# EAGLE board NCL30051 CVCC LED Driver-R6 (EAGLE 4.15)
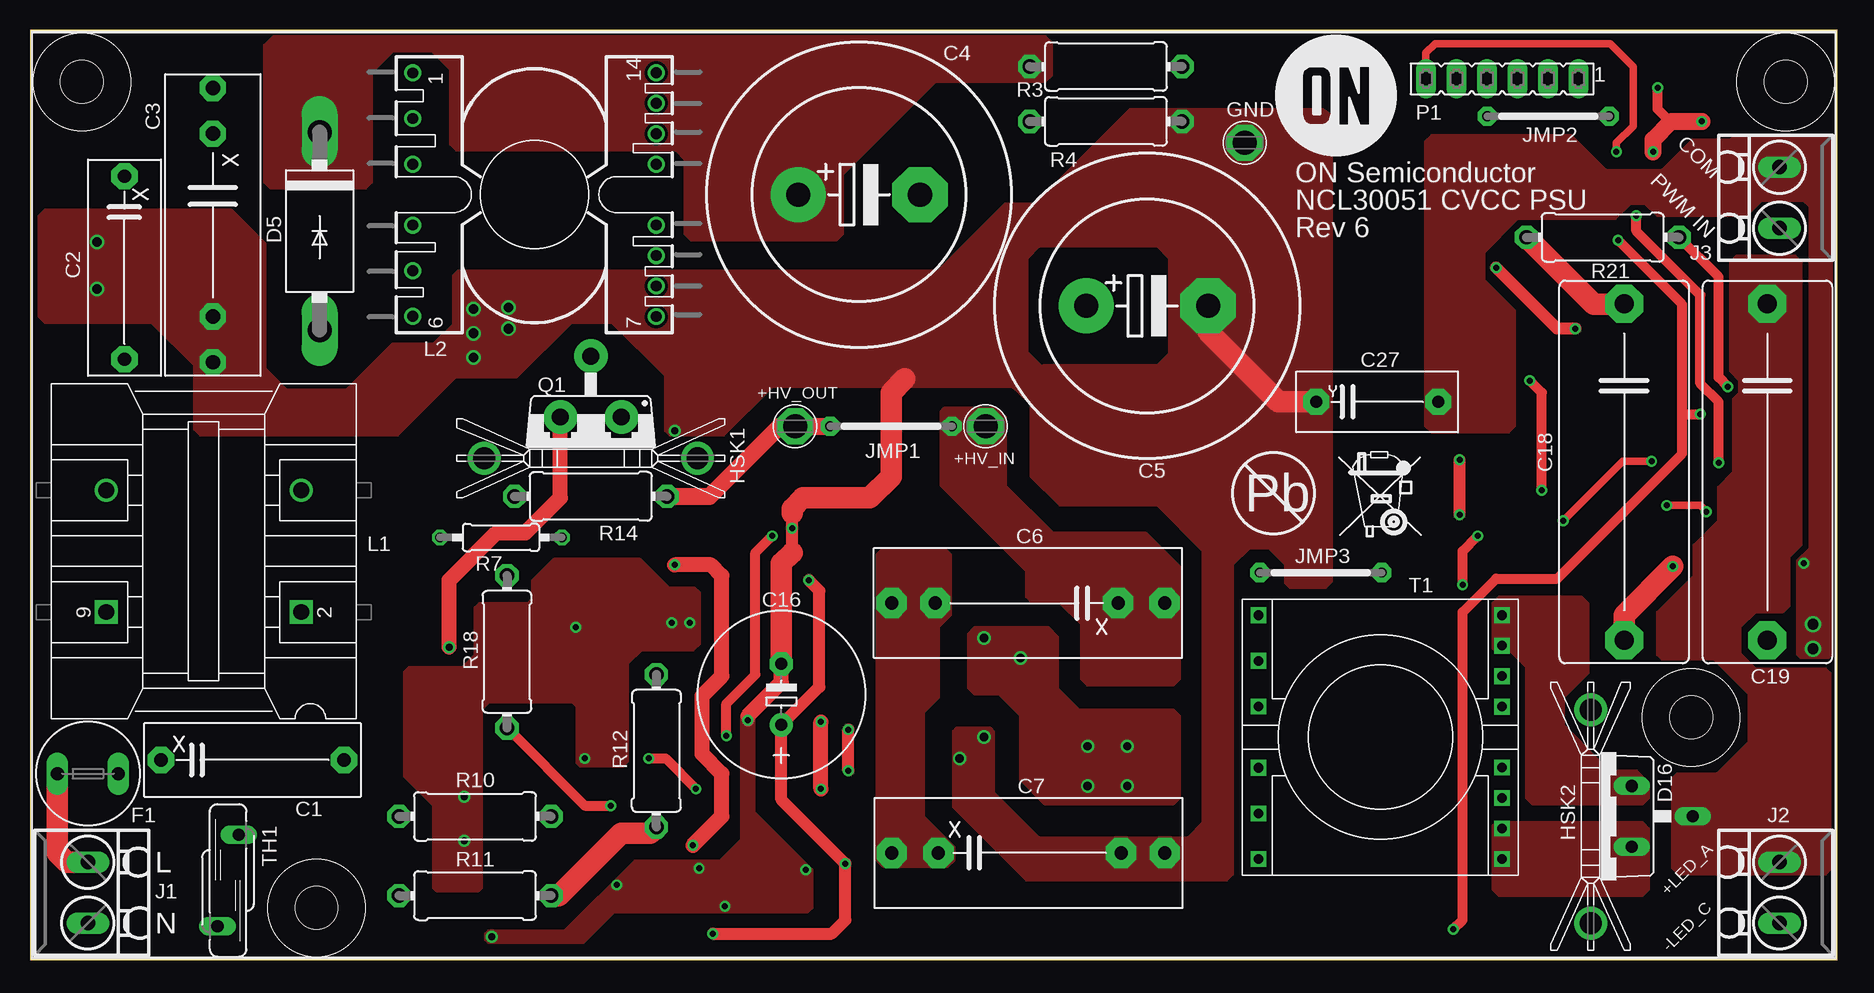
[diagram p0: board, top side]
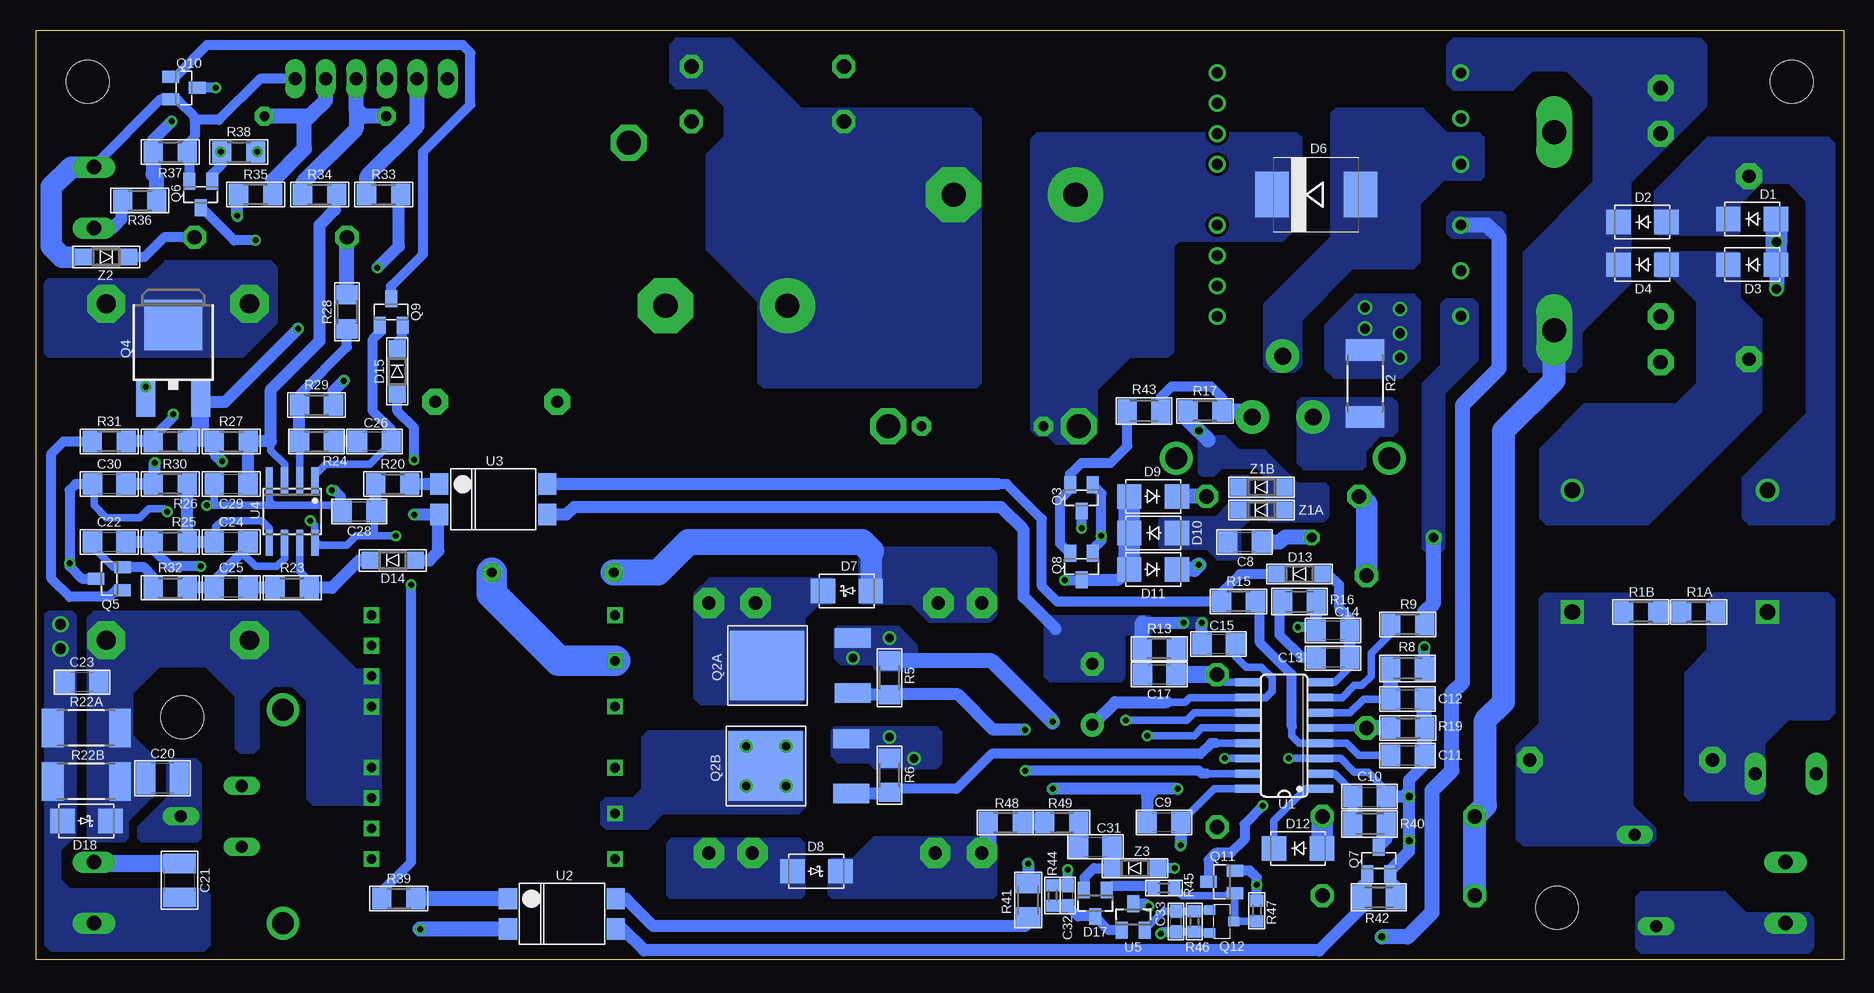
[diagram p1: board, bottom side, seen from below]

Size 150.62 x 77.47 mm. Coordinates in mm from the lower left corner, seen from the top.
Outline: 0,0 150.62,0 150.62,77.47 0,77.47 0,0
Copper layers (1*16): Top 0.035mm / dielectric 1.5mm / Bottom 0.035mm
Design rules "default": minimum track width 10mil, minimum drill 19mil, track to track 8mil, track to pad 8mil, pad to pad 8mil, via to via 8mil, smd to smd 8mil, copper to edge 10mil, drill to drill 8mil, minimum pad ring 10mil, minimum via ring 8mil, stop-mask expansion 4mil, vias tented up to drill 0mil, thermal gap 10mil
Holes 3.56 mm at 146.3,73.15 4.32,73.15 23.88,4.32 138.43,20.19

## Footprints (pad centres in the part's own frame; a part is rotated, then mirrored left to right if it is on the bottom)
PC_TEST_POINT = drill 2 octagon: 1 0,0
XC15B6 = drill 1.1 pad 2.184 octagon: 1 -7.62,0; 2 7.62,0
XC22.5B25X8MM = drill 1.2 pad 2.184 octagon: 1 -11.43,0; 2 11.43,0; 3 -7.62,0; 4 7.62,0
EB25D = drill 2.007 pad 4.597 round: + -5.08,0 | drill 2.007 pad 4.597 octagon: - 5.08,0
XC15_22.5B10 = drill 1.1 pad 2.54 octagon: 1 -7.62,0; 2 7.62,0; 3 -11.5,0; 4 11.25,0
C1206 = smd 1.6 x 1.8: 1 -1.4,0; 2 1.4,0
E5-13 = drill 1 pad 1.93 round: + -2.54,0 | drill 1 pad 1.93 octagon: - 2.54,0
C280-11X32 = drill 1.6 pad 3.175 octagon: 1 -14.016,0; 2 14.016,0
C1210 = smd 1.6 x 2.7: 1 -1.4,0; 2 1.4,0
YC10B5 = drill 1.016 pad 2.184 octagon: 1 -5.08,0; 2 5.08,0
C0603 = smd 1.1 x 1: 1 -0.85,0; 2 0.85,0
SMA-DIODE = smd 2.032 x 2.032: A 1.994,0; C -1.994,0
DO201-15 = drill 2 long: A 8.255,0; C -8.255,0
SMC = smd 2.8 x 3.8: A 3.7,0; C -3.7,0
SMA = smd 2.032 x 2.032: A 1.994,0; C -1.994,0
SOD123 = smd 1.4 x 1.4: A 1.9,0; C -1.9,0
TO220CSH = drill 1.016 long: A1 -2.54,-2.54; A2 2.54,-2.54; C 0,-7.62
SOT23 = smd 1 x 1.4: 1 -0.95,-1.1; 2 0.95,-1.1; 3 0,1.1
TR5 = drill 1.1 pad 1.778 long: 1 -2.54,0; 2 2.54,0
AAVID-542502D00000 = drill 1.829 round: 1 -8.89,0; 2 8.89,0
2-PIN = drill 1.2 long: + -2.54,0; - 2.54,0
10 = drill 0.813 pad 1.6 octagon: 1 -5.08,0; 2 5.08,0
E3491-AL = drill 1.3 square: 2 -5.08,-8.128; 9 -5.08,8.128 | drill 1.3 round: 4 5.08,-8.128; 7 5.08,8.128
PQ20/20 = drill 0.9 round: 1 -10.14,-10.15; 2 -6.34,-10.15; 3 -2.54,-10.15; 4 2.54,-10.15; 5 6.34,-10.15; 6 10.14,-10.15; 7 10.16,10.15; 8 7.62,10.15; 9 5.08,10.15; 10 2.54,10.15; 11 -2.54,10.15; 12 -5.08,10.15; 13 -7.62,10.15; 14 -10.16,10.15
FE06 = drill 1.1 pad 1.422 long: 1 -6.35,0; 2 -3.81,0; 3 -1.27,0; 4 1.27,0; 5 3.81,0; 6 6.35,0
IW220-BENT = drill 1.4 pad 2.794 round: D 0,-7.62; G -2.54,-2.54; S 2.54,-2.54
DPAK = smd 1.6 x 2.997: 1 -2.286,-4.064; 3 2.286,-4.064 | smd 5.791 x 6.198: 4 0,3.099
SOT23-BEC = smd 1 x 1.4: B -0.95,-1.1; C 0,1.1; E 0.95,-1.1
DPAK' = smd 1.6 x 3: 1 -2.28,-4.04; 3 2.28,-4.04 | smd 4.826 x 4.191: 4 0,2.096
SOT-23 = smd 1 x 1.4: D 0,1.1; G -0.95,-1.1; S 0.95,-1.1
MICRO3 = smd 0.8 x 0.9: 1 -0.95,-1; 2 0.95,-1; 3 0,1
R1206 = smd 1.6 x 1.803: 1 -1.422,0; 2 1.422,0
R2512 = smd 1.8 x 3.2: 1 -2.8,0; 2 2.8,0
0411/12 = drill 1.2 pad 1.93 octagon: 1 -6.35,0; 2 6.35,0
0207/10 = drill 0.813 octagon: 1 -5.08,0; 2 5.08,0
M1206 = smd 1.6 x 2: 1 -1.4,0; 2 1.4,0
R0603 = smd 1 x 1.1: 1 -0.85,0; 2 0.85,0
PQ20/20' = drill 0.8 square: 1 -10.16,-10.15; 2 -6.36,-10.15; 3 -2.55,-10.15; 4 2.55,-10.15; 5 6.36,-10.15; 6 10.16,-10.15; 7 10.16,10.15; 8 7.62,10.15; 9 5.08,10.15; 10 2.54,10.15; 11 -2.54,10.15; 12 -5.08,10.15; 13 -7.62,10.15; 14 -10.16,10.15
S10K17 = drill 1.016 long: 1 -0.889,-3.81; 2 0.889,3.81
SOIC16 = smd 0.66 x 2.032: 1 -4.445,-3.073; 2 -3.175,-3.073; 3 -1.905,-3.073; 4 -0.635,-3.073; 5 0.635,-3.073; 6 1.905,-3.073; 7 3.175,-3.073; 8 4.445,-3.073; 9 4.445,3.073; 10 3.175,3.073; 11 1.905,3.073; 12 0.635,3.073; 13 -0.635,3.073; 14 -1.905,3.073; 15 -3.175,3.073; 16 -4.445,3.073
4PIN-SURFMOUNT-OPTO = smd 1.524 x 1.778: 1 4.496,-1.27; 2 4.496,1.27; 3 -4.496,1.27; 4 -4.496,-1.27
SO08 = smd 0.6 x 2.2: 1 -1.905,-2.6; 2 -0.635,-2.6; 3 0.635,-2.6; 4 1.905,-2.6; 5 1.905,2.6; 6 0.635,2.6; 7 -0.635,2.6; 8 -1.905,2.6
SOT-23' = smd 1 x 1.4: 1 -0.95,-1.1; 2 0.95,-1.1; 3 0,1.1

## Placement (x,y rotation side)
+HV_IN  TP5010-5014  [PC_TEST_POINT]  79.63,44.45 0 top
+HV_OUT  TP5010-5014  [PC_TEST_POINT]  63.75,44.45 0 top
C1  0.1uF  [XC15B6]  18.54,16.64 0 top
C2  0.1uF  [XC15B6]  7.87,57.66 270 top
C3  0.1uF  [XC22.5B25X8MM]  15.24,61.21 270 top
C4  150uF/400V  [EB25D]  69.09,63.75 0 top
C5  150uF/400V  [EB25D]  93.09,54.48 0 top
C6  0.1uF/400V  [XC15_22.5B10]  83.06,29.72 180 top
C7  0.1uF/400V  [XC15_22.5B10]  83.31,8.89 0 top
C8  5.6nF  [C1206]  49.91,34.8 180 bottom
C9  0.22uF  [C1206]  56.64,11.43 180 bottom
C10  820pF  [C1206]  39.5,13.59 0 bottom
C11  0.1uF  [C1206]  36.32,17.02 0 bottom
C12  100pF  [C1206]  36.32,21.72 0 bottom
C13  0.68uF  [C1206]  42.55,25.15 180 bottom
C14  1nF  [C1206]  42.55,27.43 180 bottom
C15  0.1uF  [C1206]  52.07,26.29 180 bottom
C16  330uF/35V  [E5-13]  62.61,22.1 90 top
C17  1.2nF  [C1206]  57.02,23.75 180 bottom
C18  4.7uF/100V  [C280-11X32]  132.84,40.64 270 top
C19  4.7uF/100V  [C280-11X32]  144.78,40.64 270 top
C20  0.1uF/100V  [C1210]  140.08,15.11 180 bottom
C21  0.1uF/100V  [C1210]  138.68,6.6 270 bottom
C22  1.0uF  [C1206]  144.53,34.8 180 bottom
C23  0.1uF  [C1206]  146.81,23.11 180 bottom
C24  1nF  [C1206]  134.37,34.8 180 bottom
C25  1.0uF  [C1206]  134.37,30.99 180 bottom
C26  0.1uF  [C1206]  122.43,43.18 180 bottom
C27  2.2nF/1KV  [YC10B5]  112.27,46.48 0 top
C28  1.0uF  [C1206]  123.7,37.34 180 bottom
C29  10nF  [C1206]  134.37,39.62 180 bottom
C30  0.1uF  [C1206]  144.53,39.62 180 bottom
C31  220pF  [C1206]  62.36,9.4 0 bottom
C32  100nF  [C0603]  64.64,5.33 90 bottom
C33  220pF  [C0603]  55.63,3.18 90 bottom
D1  MRA4007  [SMA-DIODE]  7.62,61.72 0 bottom
D2  MRA4007  [SMA-DIODE]  16.76,61.47 0 bottom
D3  MRA4007  [SMA-DIODE]  7.62,57.91 0 bottom
D4  MRA4007  [SMA-DIODE]  16.76,57.91 0 bottom
D5  1N5406  [DO201-15]  24.13,60.71 270 top
D6  MURS360BT  [SMC]  43.94,63.75 0 bottom
D7  MURA160  [SMA]  83.06,30.73 0 bottom
D8  MURA160  [SMA]  85.6,7.37 180 bottom
D9  MRA4007  [SMA-DIODE]  57.53,38.61 180 bottom
D10  MURA160  [SMA-DIODE]  57.53,35.56 0 bottom
D11  MURA160  [SMA-DIODE]  57.53,32.51 180 bottom
D12  MRA4007  [SMA-DIODE]  45.47,9.27 0 bottom
D13  MMSD4148T  [SOD123]  45.34,32.13 0 bottom
D14  MMSD4148T  [SOD123]  120.9,33.27 0 bottom
D15  MMSD4148T  [SOD123]  120.52,49.02 270 bottom
D16  MBRF10H150  [TO220CSH]  130.94,11.94 90 top
D17  BAV70  [SOT23]  62.36,4.7 180 bottom
D18  MBRA340  [SMA]  146.43,11.56 180 bottom
E$2  [ON2]  108.84,72.01 0 top
F1  1.5A  [TR5]  4.83,15.49 0 top
GND  TP5010-5014  [PC_TEST_POINT]  101.22,68.07 0 top
HSK1  AAVID-542502D00000  [AAVID-542502D00000]  46.74,41.78 180 top
HSK2  AAVID-542502D00000  [AAVID-542502D00000]  130.05,11.94 90 top
J1  [2-PIN]  4.83,5.59 270 top
J2  [2-PIN]  145.8,5.59 90 top
J3  [2-PIN]  145.8,63.5 90 top
JMP1  J10MM  [10]  71.76,44.45 0 top
JMP2  J10MM  [10]  126.52,70.28 0 top
JMP3  J10MM  [10]  107.57,32.26 0 top
L1  2.9mH  [E3491-AL]  14.48,34.04 90 top
L2  700uH  [PQ20/20]  42.04,63.75 270 top
P1  [FE06]  122.68,73.41 180 top
Q1  SPP11N60C3  [IW220-BENT]  46.74,42.67 180 top
Q2A  NDD04N60ZT  [DPAK]  86.61,24.51 90 bottom
Q2B  NDD04N60ZT  [DPAK]  86.74,16.13 90 bottom
Q3  MMBT2907A  [SOT23-BEC]  63.5,38.48 180 bottom
Q4  MJD243G  [DPAK']  139.19,50.8 0 bottom
Q5  2N7002KT1G  [SOT23]  144.53,31.75 90 bottom
Q6  MMBTA06LT1G  [SOT23-BEC]  136.91,63.75 180 bottom
Q7  MMBTA06LT1G  [SOT23-BEC]  38.74,8.26 0 bottom
Q8  MMBTA06LT1G  [SOT23-BEC]  63.5,32.77 180 bottom
Q9  MMBT2907A  [SOT23-BEC]  121.03,53.98 0 bottom
Q10  MMUN2212L  [SOT23-BEC]  138.3,72.64 270 bottom
Q11  2N7002  [SOT-23]  51.82,6.48 90 bottom
Q12  BSS84  [MICRO3]  51.82,3.18 270 bottom
R1A  560K  [R1206]  12.07,28.96 0 bottom
R1B  560K  [R1206]  16.89,28.96 0 bottom
R2  0.15/0.5W  [R2512]  39.88,48.01 270 bottom
R3  560K/0.5W  [0411/12]  89.66,74.42 180 top
R4  560K/0.5W  [0411/12]  89.66,69.85 180 top
R5  10K  [R1206]  79.5,23.5 270 bottom
R6  10K  [R1206]  79.5,15.37 270 bottom
R7  10/0.25W  [0207/10]  39.24,35.18 180 top
R8  1.2K  [M1206]  36.32,24.26 0 bottom
R9  26.7K  [R1206]  36.32,27.94 0 bottom
R10  4.7K/0.5W  [0411/12]  37.08,11.94 0 top
R11  680K/0.5W  [0411/12]  37.08,5.33 180 top
R12  680K/0.5W  [0411/12]  52.2,17.4 270 top
R13  OPEN  [R1206]  57.02,25.91 0 bottom
R14  2.7M/0.5W  [0411/12]  46.74,38.61 0 top
R15  2.7K  [R1206]  50.42,29.85 0 bottom
R16  1K  [M1206]  45.34,29.85 180 bottom
R17  10K  [R1206]  53.21,45.72 0 bottom
R18  2.7M/0.5W  [0411/12]  39.75,25.65 90 top
R19  26.7K  [R1206]  36.32,19.3 180 bottom
R20  2.2K  [R1206]  120.9,39.62 180 bottom
R21  4.7K/0.5W  [0411/12]  131.06,60.2 0 top
R22A  0.1/0.5W  [R2512]  146.43,19.3 180 bottom
R22B  0.1/0.5W  [R2512]  146.43,14.86 180 bottom
R23  100K  [R1206]  129.29,30.99 180 bottom
R24  100K  [R1206]  127.25,43.18 180 bottom
R25  2.7K  [R1206]  139.45,34.8 180 bottom
R26  68K  [R1206]  139.45,39.62 0 bottom
R27  6.2K  [R1206]  134.37,43.18 180 bottom
R28  78.7K  [R1206]  124.71,53.98 90 bottom
R29  3.9K  [R1206]  127.25,46.23 180 bottom
R30  5.1K  [R1206]  139.45,43.18 180 bottom
R31  100  [R1206]  144.53,43.18 0 bottom
R32  2.7K  [R1206]  139.45,30.99 180 bottom
R33  10  [R1206]  121.67,63.75 180 bottom
R34  10  [R1206]  127,63.75 180 bottom
R35  10  [R1206]  132.33,63.75 0 bottom
R36  10K  [R1206]  141.99,63.25 180 bottom
R37  10K  [R1206]  139.45,67.31 180 bottom
R38  10K  [R1206]  133.73,67.31 180 bottom
R39  2.7K  [R1206]  120.4,5.08 180 bottom
R40  1.2K  [M1206]  39.5,11.3 0 bottom
R41  10K  [M1206]  67.95,4.95 270 bottom
R42  5.1K  [M1206]  38.74,5.21 180 bottom
R43  10  [M1206]  58.29,45.72 0 bottom
R44  10K  [R0603]  65.91,5.33 270 bottom
R45  33K  [R0603]  56.64,5.97 0 bottom
R46  4.7K  [R0603]  54.1,3.18 270 bottom
R47  33K  [R0603]  48.9,4.06 270 bottom
R48  24K  [R1206]  69.85,11.43 180 bottom
R49  24K  [R1206]  65.15,11.43 180 bottom
T1  [PQ20/20']  112.52,18.54 270 top
TH1  [S10K17]  16.51,6.6 0 top
U1  NCL30051  [SOIC16]  46.61,18.67 90 bottom
U2  SFH6156A-4  [4PIN-SURFMOUNT-OPTO]  106.81,3.81 180 bottom
U3  SFH6156A-4  [4PIN-SURFMOUNT-OPTO]  112.52,38.35 180 bottom
U4  NCS1002  [SO08]  129.29,37.34 180 bottom
U5  TLV431A  [SOT-23']  59.18,3.56 0 bottom
U$3  [WEEE_SMALL]  112.65,36.58 0 top
Z1A  MMSZ5248B  [SOD123]  48.51,37.47 0 bottom
Z1B  MMSZ5248B  [SOD123]  48.51,39.37 0 bottom
Z2  MMSZ5245B  [SOD123]  144.78,58.55 180 bottom
Z3  MMSZ5248B  [SOD123]  59.06,7.62 0 bottom

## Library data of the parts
+HV_IN +HV_OUT GND = testpad
C1-C33 R1A R1B R2-R21 R22A R22B R23-R49 = rcl
D1-D18 Z1A Z1B Z2 Z3 = diode
E$2 = loga
F1 = fuse
HSK1 HSK2 = heatsink
J1-J3 = My CONNECTOR lib
JMP1-JMP3 = jumper
L1 = MY  INDUCTOR Lib
L2 = My X-former-2
P1 = con-lsta
Q1 Q2A Q2B Q12 = transistor-power
Q3 Q9 = transistor-pnp
Q4 = transistor
Q5 = transistor-small-signal
Q6-Q8 Q10 = transistor-npn2
Q11 = transistor-fet
T1 = My X-former
TH1 = varistor
U1 U5 = My IC Lib
U2 U3 = optocoupler
U4 = linear
U$3 = My Sign Lib

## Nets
N$1: C1.1 F1.2 L1.9 R1A.2
N$2: J1.- TH1.1
N$3: C2.1 D1.C D2.A L1.7
N$4: C1.2 L1.2 R1B.1 TH1.2
N$5: C10.1 R40.1 U1.2
N$6: C2.2 D3.C D4.A L1.4
N$7: D6.A L2.3 Q1.D
N$8: Q1.S R2.2 R8.2
N$9: +HV_OUT.1 C4.+ D5.C D6.C D9.C JMP1.1 R3.2 R14.2
N$10: C3.1 C3.3 D2.C D4.C D5.A L2.1 R10.1 R11.2
N$11: C4.- C5.+ R3.1 R4.2
N$12: Q2A.1 R5.2 U1.15
N$13: Q2B.1 R6.2 U1.13
N$14: Q3.E Q8.E R43.1
N$15: L2.6 R7.2 R9.2
N$16: C9.2 Q2A.3 Q2B.4 R5.1 T1.5 U1.14
N$17: +HV_IN.1 C6.1 C6.3 D7.C JMP1.2 Q2A.4
N$18: Q3.B Q8.B U1.12
N$19: C12.1 R8.1 U1.6
N$20: C6.2 C6.4 C7.1 C7.3 D7.A D8.C JMP3.1 R48.2
N$21: C8.1 R7.1
N$22: R9.1 U1.7
N$23: D12.C U1.1
N$24: C11.1 R15.2 U1.4
N$25: R11.1 R12.2
N$26: C17.1 R12.1 R13.2 U1.9
N$27: D16.A1 T1.7 T1.8
N$28: C13.1 C14.1 D13.A U1.8
N$29: C13.2 R16.2
N$30: Q1.G R17.2 R43.2
N$31: R14.1 R18.2
N$32: C21.2 C23.2 C27.2 C28.2 C29.2 C30.2 D18.A J2.+ J3.- P1.1 Q5.3 Q6.E Q10.E R22A.2 R22B.2 R29.1 R37.1 U4.4 Z2.A
N$33: C8.2 D10.A Z1A.C Z1B.C
N$34: Q7.C R40.2
N$35: C15.1 C16.+ C33.1 D9.A D10.C D11.A Q8.C Q12.2 R41.1 R46.2 U1.10
N$36: C9.1 D11.C U1.16
N$37: R39.1 U2.1
N$38: Q11.D R18.1 R19.2 U1.5
N$39: Q6.C R30.2 R31.2 U2.2
N$40: R20.1 U3.1
N$41: D14.A D15.A U3.2
N$42: C18.2 C19.2 C20.2 C22.1 C23.1 D18.C R22A.1 R22B.1 R25.2 T1.9 T1.10 T1.11 T1.12
N$43: D16.A2 T1.13 T1.14
N$44: C3.2 C3.4 C5.- C7.2 C7.4 C10.2 C11.2 C12.2 C14.2 C15.2 C16.- C17.2 C27.1 C32.2 D1.A D3.A D8.A GND.1 L2.4 Q2B.3 Q3.C Q7.E Q11.S R2.1 R4.1 R6.1 R13.1 R16.1 R17.1 R19.1 R42.1 R44.1 R47.1 U1.3 U1.11 U3.3 U5.3 Z1A.A Z1B.A Z3.A
N$45: D13.C R15.1 U3.4
N$46: F1.1 J1.+
N$47: D14.C R23.1 U4.7
N$48: D12.A R10.2
N$49: Q7.B R42.2 U2.3
N$50: C29.1 R27.1 R34.1 U4.3
N$51: C30.1 R26.1 R35.1
N$52: C25.1 R23.2
N$53: C24.1 C25.2 R32.1 U4.6
N$54: Q4.1 R21.2 Z2.C
N$55: C26.1 Q9.B U4.1
N$56: C28.1 Q4.3 R20.2 R27.2 R30.1 R33.1 R39.2 U4.8
N$57: C26.2 R24.1
N$58: R24.2 R28.1 R29.2 U4.2
N$59: C24.2 R25.1 R26.2 U4.5
N$60: R41.2 U2.4
N$61: C22.2 Q5.2 R32.2
N$62: Q5.1 R31.1
N$63: Q6.B Q10.C R36.1 R37.2 R38.2
N$64: JMP3.2 T1.2
N$65: J3.+ R36.2
N$66: JMP2.2 P1.2 R35.2
N$67: JMP2.1 P1.3 R34.2
N$68: C18.1 C19.1 C20.1 C21.1 D16.C J2.- Q4.4 R21.1 R28.2
N$69: P1.5 R33.2
N$70: P1.6 R38.1
N$71: R1A.1 R1B.2
N$72: D15.C Q9.E
N$73: R48.1 R49.2
N$74: C31.1 R49.1
N$75: Q9.C Q10.B
N$76: C31.2 D17.2 Z3.C
N$77: C32.1 D17.3 R44.2 U5.1
N$79: D17.1 R45.1
N$80: Q11.G Q12.3 R45.2 R47.2
N$81: C33.2 Q12.1 R46.1 U5.2

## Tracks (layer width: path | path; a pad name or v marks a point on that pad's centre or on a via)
N$1
  pour Bottom (no thermals): 6.6,13.72 6.6,18.03 4.57,20.07 1.27,20.07 0.76,20.57 0.76,29.97 1.27,30.48 10.8,30.48 11.3,29.97 11.3,25.78 13.21,23.88 13.21,13.72 12.83,13.34 6.99,13.34
N$2
  pour Bottom (no thermals): 16.89,0.64 2.92,0.64 2.54,1.02 2.54,3.43 2.92,3.81 8.13,3.81 9.91,5.59 16.89,5.59 17.27,5.21 17.27,1.02
N$3
  pour Bottom (no thermals): 6.86,64.77 4.57,64.77 3.05,63.25 3.05,45.47 8.38,40.13 8.38,36.83 7.87,36.32 1.27,36.32 0.76,36.83 0.76,67.95 1.27,68.45 11.3,68.45 15.75,64.01 15.75,60.71 15.49,60.45 8.89,60.45 8.64,60.71 8.64,62.99
N$4
  pour Bottom (no thermals): 26.67,9.53 27.18,10.03 27.18,17.78 25.27,19.69 25.27,30.1 24.89,30.48 18.03,30.48 17.65,30.1 17.65,12.83 15.75,10.92 15.75,10.03 16.26,9.53
N$5
  Bottom 0.61: C10.1 40.89,13.97 42.42,15.49 U1.2
  Bottom 0.813: R40.1 C10.1
N$6
  pour Bottom (isolate 1.27, no thermals): 16.26,36.32 6.86,45.72 6.86,53.34 8.64,55.12 8.64,58.67 8.89,58.93 15.49,58.93 15.75,58.67 15.75,57.15 15.49,56.9 14.22,56.9 12.19,54.86 12.19,48.01 13.97,46.23 21.59,46.23 25.27,42.55 25.27,36.83 24.77,36.32
N$7
  pour Bottom (no thermals): 45.21,49.53 45.21,53.34 40.89,57.66 35.81,57.66 35.31,58.17 35.31,62.99 33.27,65.02 30.23,65.02 29.97,65.28 29.97,68.45 30.35,68.83 33.02,68.83 35.05,70.87 42.29,70.87 42.67,70.49 42.67,60.2 48.26,54.61 48.26,49.53 47.75,49.02 45.72,49.02
N$8  (via drill 0.6)
  Top 1.27: Q1.S 44.2,38.48 41.28,35.56 38.86,35.56 34.93,31.62 v34.93,26.04
  Bottom 1.016: R8.2 v34.93,26.04
  Bottom 1.27: R8.2
  pour Bottom (no thermals): 38.61,43.69 37.59,43.69 37.21,44.07 37.21,46.36 37.59,46.74 45.21,46.74 45.47,46.48 45.47,41.4 44.96,40.89 40.13,40.89 39.88,41.15 39.88,42.42
N$9
  Top 1.422: R14.2 56.64,38.61 62.48,44.45 +HV_OUT.1 JMP1.1
  Bottom 1.27: R14.2 D9.C
  pour Top (isolate 0.254, no thermals): 19.56,64.77 19.56,76.2 20.32,76.96 84.58,76.96 85.09,76.45 85.09,73.66 84.58,73.15 75.44,73.15 67.69,65.41 67.69,60.45 67.18,59.94 55.12,59.94 54.61,60.45 54.61,66.68 53.85,67.44 35.56,67.44 35.05,67.95 35.05,74.17 33.53,75.69 30.23,75.69 28.45,73.91 28.45,64.77 27.94,64.26 20.07,64.26
  pour Bottom (isolate 0.254, no thermals): 45.21,61.47 45.21,68.45 45.59,68.83 67.18,68.83 67.69,68.33 67.69,44.2 67.18,43.69 66.29,43.69 65.66,43.05 63.25,43.05 62.23,44.07 62.23,47.5 59.44,50.29 56.26,50.29 55.88,50.67 55.88,59.44 55.37,59.94 46.74,59.94
N$10
  Bottom 1.93: R11.2 R10.1 29.85,12.83 29.85,19.94 28.32,21.46 28.32,44.07 24.13,48.26 D5.A
  pour Bottom (no thermals): 17.78,56.39 17.78,64.77 11.43,71.12 11.43,76.2 11.94,76.71 32.51,76.71 33.02,76.2 33.02,73.03 32.51,72.52 27.56,72.52 25.91,74.17 23.11,74.17 20.83,71.88 20.83,64.77 26.67,58.93 26.67,49.53 26.16,49.02 22.35,49.02 21.84,49.53 21.84,52.32
N$11
  pour Bottom (no thermals): 71.88,48.13 71.88,70.1 72.64,70.87 86.87,70.87 92.71,76.71 97.28,76.71 97.79,76.2 97.79,73.15 97.28,72.64 94.74,72.64 93.22,71.12 93.22,68.58 94.74,67.06 94.74,59.18 90.42,54.86 90.42,48.13 90.04,47.75 81.41,47.75 72.26,47.75
N$12  (via drill 0.5)
  Top 1.016: v68.2,15.75 v68.2,19.18
  Bottom 0.61: U1.15 53.09,15.49
  Bottom 0.813: 79.5,22.1 R5.2 | 53.09,15.49 53.47,15.49 53.72,15.75 v68.2,15.75
  Bottom 1.016: 79.5,22.1 73.79,22.1 70.87,19.18 v68.2,19.18 | Q2A.1 82.55,22.1 82.53,22.07 R5.2
N$13
  Bottom 0.61: U1.13 52.32,18.03
  Bottom 0.813: Q2B.1 82.8,13.97 | R6.2 79.53,13.95 | R6.2 79.4,13.95 79.12,14.22 73.91,14.22 70.99,17.15 53.59,17.15 52.71,18.03 52.32,18.03 | R6.2 79.5,13.84
  Bottom 1.016: 79.5,13.84 Q2B.1 82.8,13.84
N$14
  Bottom 0.813: Q8.E 64.45,33.84 65.28,34.67 65.28,38.35 64.39,39.24 64.45,39.3 64.45,39.56 64.47,39.58 | 64.47,39.58 64.52,39.62 | 64.47,39.58 Q3.E 64.45,40.45 63.5,41.4 61.09,41.4 59.69,42.8 R43.1
N$15
  Bottom 1.27: R9.2 34.93,27.94 34.93,28.96 34.16,29.72 R7.2
  pour Bottom (no thermals): 33.27,34.29 33.27,47.24 30.48,50.04 30.48,54.61 30.86,54.99 33.15,54.99 33.53,54.61 33.53,49.53 35.05,48.01 35.05,34.29 34.8,34.04 33.53,34.04
N$16  (via drill 0.5, 0.7)
  Top 0.813: v51.56,16.76 52.96,16.76 v55.5,14.22
  Top 1.27: v65.91,14.22 v65.91,19.81
  Bottom 0.61: U1.14 v51.56,16.76
  Bottom 0.813: 58.04,11.81 C9.2
  Bottom 1.016: 57.4,14.22 v65.91,14.22 | v55.5,14.22 57.4,14.22 | 58.04,11.81 58.04,13.59 57.4,14.22
  Bottom 1.27: v65.91,19.81 70.99,24.89 79.5,24.89 R5.1
  other vias: 79.5,26.8 88.14,17.78 91.44,17.78 88.14,14.48 91.44,14.48 82.55,25.15
  pour Top (no thermals): 95.25,12.95 84.58,12.95 82.55,14.99 82.55,20.32 80.77,22.1 78.74,22.1 78.23,22.61 78.23,27.18 78.74,27.69 84.84,27.69 85.6,26.92 85.6,22.61 87.38,20.83 95.25,20.83 95.76,20.32 95.76,13.46
  pour Bottom (no thermals): 87.12,12.19 98.43,12.19 99.7,10.92 103.12,10.92 103.51,11.3 103.51,13.08 103.12,13.46 100.84,13.46 100.08,14.22 100.08,18.54 99.57,19.05 86.87,19.05 86.61,18.8 86.61,12.7
  pour Bottom (no thermals): 77.22,26.16 78.74,27.69 83.82,27.69 84.07,27.43 84.07,25.15 83.57,24.64 81.03,24.64 80.52,24.13 77.6,24.13 77.22,24.51
N$17
  pour Bottom (no thermals): 86.61,21.84 86.61,28.45 85.34,29.72 84.33,29.72 84.07,29.97 84.07,31.5 84.33,31.75 94.49,31.75 95.76,30.48 95.76,21.84 95.25,21.34 87.12,21.34
  pour Top (no thermals): 95.25,22.86 88.14,22.86 87.63,23.37 87.63,27.94 85.85,29.72 83.57,29.72 83.06,30.23 83.06,32.39 75.95,39.5 75.95,45.72 76.2,45.97 80.52,45.97 81.28,45.21 81.28,39.5 85.22,35.56 92.96,35.56 95.76,32.77 95.76,23.37
N$18  (via drill 0.5)
  Top 0.813: v61.85,35.31 60.45,33.91 60.45,23.75 58.04,21.34 v58.04,18.67
  Bottom 0.61: U1.12 53.47,19.3 54.1,18.67 v58.04,18.67
  Bottom 0.813: Q3.B 62.55,39.56 61.85,38.86 v61.85,35.31 61.85,34.93 62.55,34.22 Q8.B
N$19
  Bottom 0.61: U1.6 41.15,20.57 40.01,21.72 C12.1
  Bottom 1.016: R8.1 37.59,24.26 37.72,24.13
  Bottom 1.27: C12.1 37.72,24.13
N$20
  Bottom 1.422: C7.3 71.76,8.89 71.27,9.37 R48.2
  Bottom 1.778: D7.A 81.03,30.73 81.03,34.04
  Bottom 2.184: JMP3.1 98.81,32.26 96.27,34.8 81.79,34.8 81.03,34.04
  pour Bottom (no thermals): 70.61,28.7 70.61,33.78 71.12,34.29 81.53,34.29 82.04,33.78 82.04,29.97 81.79,29.72 77.72,29.72 76.2,28.19 71.12,28.19
  pour Bottom (no thermals): 70.61,5.46 70.61,9.65 71.12,10.16 80.77,10.16 82.55,8.38 84.33,8.38 84.58,8.13 84.58,5.46 84.33,5.21 70.87,5.21
  pour Top (no thermals): 70.61,8.26 70.61,33.78 71.12,34.29 76.2,34.29 76.71,33.78 76.71,28.7 75.69,27.69 75.69,21.84 74.42,20.57 74.42,11.94 76.96,9.4 76.96,8.26 76.45,7.75 71.12,7.75
N$21
  Bottom 1.27: R7.1 46.61,35.18 46.99,34.8 C8.1
N$22
  Bottom 0.61: U1.7 41.78,21.84 40.77,22.86 40.13,22.86 39.37,23.62 39.37,25.53 37.72,27.18 37.72,27.94 R9.1
N$23
  Bottom 0.61: U1.1 44.83,14.22 47.5,11.56 47.5,9.27 D12.C
N$24
  Bottom 0.61: C11.1 40.39,17.02 41.4,18.03 U1.4 45.34,18.03 45.97,18.67 45.97,19.43
  Bottom 0.813: 45.97,19.43 45.97,23.75 48.64,26.42 48.64,29.46 49.02,29.85 R15.2
N$25
  Top 1.778: R12.2 51.69,10.54 49.28,10.54 44.07,5.33 R11.1
N$26
  Bottom 0.61: U1.9 51.56,23.11 R12.1
  Bottom 1.422: R12.1 C17.1 55.6,23.77 R13.2
N$27
  pour Top (no thermals): 121.92,5.84 121.92,11.18 122.17,11.43 134.37,11.43 134.87,10.92 134.87,5.84 134.37,5.33 122.43,5.33
N$28
  Bottom 0.61: U1.8 42.42,23.11 41.15,24.38 C13.1
  Bottom 0.813: C14.1 41.15,28.45 42.04,29.34 42.04,31.24 42.93,32.13 D13.A
  Bottom 1.016: C14.1 C13.1
N$29
  Bottom 0.813: C13.2 45.09,25.15 46.99,27.05 46.99,29.59 R16.2
N$30
  Bottom 0.813: R43.2 56.89,46.87 56.01,47.75 52.71,47.75 51.82,46.86 51.82,45.72
  Bottom 1.27: Q1.G 49.78,45.72 51.82,45.72 R17.2
N$31
  Bottom 1.778: R18.2 39.75,37.97 R14.1
N$32  (via drill 0.5, 0.9)
  Top 0.61: v136.4,37.85 139.19,37.85 v139.7,37.34
  Top 0.813: v124.97,48.26 125.98,47.24 v125.98,39.12
  Bottom 0.61: 125.22,37.34 125.48,37.34 125.98,37.85 130.81,37.85 | 130.81,37.85 136.14,37.85 | U4.4 131.19,38.23 130.81,37.85 | v139.7,37.34 139.95,37.59 141.22,37.59 141.99,36.83 144.78,36.83 145.8,37.85 145.8,39.37 146.05,39.62 | 136.14,37.85 v136.4,37.85 | C29.2 135.77,38.22 136.14,37.85
  Bottom 0.813: C30.2 146.05,39.62 147.32,39.62 147.83,39.12 v147.83,33.02 147.83,32.77 146.81,31.75 Q5.3 | v125.98,39.12 125.73,39.12 125.22,38.61 125.22,37.34 C28.2 | Q6.E 137.86,67.12 138.05,67.31 R37.1 138.02,67.97 137.41,68.58 137.41,69.98 | J3.- 145.8,66.17 140.27,71.69 Q10.E 139.39,71.69 139.32,71.63 138.81,71.63 137.41,70.23 137.41,69.98 | P1.1 131.95,73.41 135.38,69.98 137.41,69.98
  Bottom 1.016: R29.1 125.83,47.4 v124.97,48.26 | 147.83,58.55 Z2.A
  Bottom 1.27: R37.1 137.92,67.31
  Bottom 1.778: J3.- 147.7,66.04 149.35,64.39 149.35,59.44 148.46,58.55 147.83,58.55
  other vias: 148.59,27.94 148.59,25.91
  pour Bottom (no thermals): 136.65,5.84 147.83,5.84 148.59,6.6 148.59,9.14 147.32,10.41 147.32,28.7 147.57,28.96 149.61,28.96 149.86,28.7 149.86,1.27 149.35,0.76 136.65,0.76 136.14,1.27 136.14,5.33
  pour Top (no thermals): 116.33,44.45 116.33,68.2 116.84,68.71 128.4,68.71 131.32,65.79 136.02,65.79 138.56,68.33 141.73,68.33 141.99,68.58 149.73,68.58 150.11,68.2 150.11,25.4 149.86,25.15 147.57,25.15 147.32,25.4 147.32,33.27 148.34,34.29 148.34,62.74 147.83,63.25 144.27,63.25 143,61.98 135.64,61.98 134.62,62.99 133.35,62.99 132.08,61.72 123.95,61.72 121.16,58.93 121.16,56.64 123.7,54.1 123.7,44.45 123.19,43.94 116.84,43.94
N$33
  pour Bottom (no thermals): 51.18,40.13 51.18,37.97 52.32,36.83 56.77,36.83 57.02,36.58 57.02,34.54 56.77,34.29 53.09,34.29 52.2,33.4 50.67,33.4 50.29,33.78 50.29,35.94 49.53,36.7 49.53,40.13 49.66,40.26 51.05,40.26
N$34
  Bottom 1.016: Q7.C 38.74,9.4 38.1,10.03 R40.2
N$35  (via drill 0.5)
  Top 1.016: v64.9,31.62 65.79,30.73 65.79,22.73 C16.+ 62.61,13.34 v67.95,8 67.95,3.3 66.8,2.16 v56.9,2.16
  Bottom 0.61: 56.39,21.46 54.86,21.46 54.48,21.84 U1.10 48.13,21.84 47.63,22.35 47.63,23.5 48.51,24.38 49.78,24.38 50.67,25.27 C15.1 | Q12.2 54.04,2.23 54.1,2.29 R46.2 55.59,2.33 55.63,2.29 C33.1
  Bottom 0.813: Q8.C 63.5,31.62 v64.9,31.62 | 55.63,2.29 56.77,2.29 v56.9,2.16
  Bottom 1.016: R41.1 v67.95,8 | D11.A 59.56,32.51 60.41,31.67 Q8.C | 56.39,21.46 60.71,21.46 C16.+
  Bottom 1.778: D9.A 59.53,35.6 59.56,35.56 D10.C 59.53,32.6 59.44,32.51 D11.A
N$36  (via drill 0.5)
  Top 1.27: v53.72,32.89 56.77,32.89 57.66,32 57.66,23.62 56.01,21.97 56.01,17.15 57.66,15.49 57.66,11.94 v55.25,9.53
  Bottom 0.61: U1.16 52.45,14.22 C9.1
  Bottom 1.016: C9.1 v55.25,9.53
  Bottom 1.27: D11.C 54.1,32.51 v53.72,32.89
N$37
  Bottom 1.27: U2.1 R39.1
N$38  (via drill 0.5)
  Top 0.813: v48.39,12.83 46.23,12.83 R18.1
  Bottom 0.61: R18.1 U1.5
  Bottom 0.813: Q11.D 52.92,8.3 52.32,8.89 51.05,8.89 49.91,10.03 49.91,11.3 v48.39,12.83
  Bottom 1.27: R19.2 R18.1
N$39  (via drill 0.5)
  Top 0.813: 137.67,45.47 137.67,54.61 v132.33,59.94 | v118.62,2.54 119.38,3.3 119.38,28.96 122.17,31.75 127.25,31.75 137.67,42.16 137.67,45.47 | 137.67,45.47 v139.19,45.47
  Bottom 0.813: R30.2 140.87,43.54 139.19,45.21 v139.19,45.47 | v132.33,59.94 134.11,59.94 136.65,62.48 136.91,62.48 Q6.C
  Bottom 1.016: R30.2 R31.2
  Bottom 1.27: U2.2 v118.62,2.54
N$40
  Bottom 1.016: U3.1 R20.1
N$41  (via drill 0.5)
  Top 1.016: v119.13,37.08 v119.13,41.66
  Bottom 0.813: v119.13,41.66 119.13,44.32 120.52,45.72 D15.A
  Bottom 1.016: D14.A 117.86,33.27 117.09,34.04 117.09,37.08 | 117.09,37.08 U3.2 | 117.09,37.08 v119.13,37.08
N$42  (via drill 0.5)
  Top 1.778: C18.2 132.84,28.7 v136.91,32.77
  Bottom 0.813: v136.91,32.77 139.45,32.77 140.72,34.04 140.72,34.54 140.97,34.8
  Bottom 1.016: R25.2 140.97,34.8 C22.1
  pour Bottom (isolate 0.406, no thermals): 121.92,13.21 121.92,23.88 122.17,24.13 123.95,24.13 128.78,28.96 145.8,28.96 146.3,28.45 146.3,10.16 146.05,9.91 143.26,9.91 143,10.16 143,11.56 140.72,13.84 140.72,16.76 142.62,18.67 142.62,22.23 140.34,24.51 136.53,24.51 133.99,21.97 133.99,17.65 133.6,17.27 132.46,17.27 132.08,17.65 132.08,21.59 130.81,22.86 129.29,22.86 128.02,21.59 128.02,13.46 127.51,12.95 122.17,12.95
N$43
  pour Top (no thermals): 121.92,25.91 121.92,29.72 122.43,30.23 129.29,30.23 129.79,29.72 129.79,23.88 127.76,21.84 127.76,19.56 131.57,15.75 133.86,15.75 134.87,14.73 134.87,13.46 134.37,12.95 125.22,12.95 124.71,13.46 124.71,24.38 123.44,25.65 122.17,25.65
N$44  (via drill 0.5, 0.6, 0.7, 0.8)
  Top 1.016: v59.82,19.94 59.82,20.32 | 63.5,37.21 v63.5,35.94 63.5,33.91
  Top 1.27: C16.- 62.61,23.11 59.82,20.32
  Top 1.778: C27.1 104.01,46.48 98.17,52.32 C5.- | 63.5,37.21 63.5,37.59 64.39,38.48 69.98,38.48 71.76,40.26 71.76,47.24 72.9,48.39 | 63.5,33.91 62.61,33.02 C16.-
  Bottom 0.61: C10.2 38.1,14.09 39.62,15.62 40.77,15.62 41.91,16.76 U1.3 v46.23,16.76 | U1.11 54.1,20.57 54.74,19.94 v59.82,19.94
  Bottom 0.813: v63.5,35.94 Q3.C | v53.47,28.06 v53.47,28.07 | C14.2 44.2,27.69 v45.47,27.69 | U5.3 58.12,4.66 v57.91,4.45 | R47.1 v48.9,6.22 48.9,6.86 49.46,7.43 Q11.S | v55.75,7.62 Z3.A | R44.1 64.68,6.18 64.64,6.22 C32.2 v64.64,7.49
  Bottom 1.016: U3.3 106.43,37.08 105.79,37.72 70.23,37.72 68.33,35.81 68.33,30.23 65.66,27.56 | R42.1 37.34,5.33 37.34,6.1 37.79,6.54 Q7.E 37.79,7.43 36.2,9.02 v36.2,9.91 36.2,14.1 | 58.42,28.07 v54.99,28.07 | C15.2 v53.47,28.06 | 36.2,14.1 36.2,14.99 34.93,16.26 C11.2 | C10.2 36.7,13.59 36.2,14.1 | R16.1 C14.2
  Bottom 1.27: D3.A 5.59,57.91 v5.59,55.88 | 52.96,43.31 v53.72,44.07 54.61,44.96 54.61,45.72 R17.1 | 34.93,16.89 34.92,16.89 C11.2 34.9,17.04 R19.1 34.93,19.3 34.92,19.31 C12.2 | C17.2 58.42,24.64 | 58.42,24.64 58.42,25.91 R13.1 58.45,27.92 58.42,27.94 58.42,28.07 | 58.42,24.64 | L2.4 29.72,61.21 28.7,60.2 28.7,49.28 31.75,46.23 31.75,23.11 32.64,22.23 32.64,15.75 34.29,14.1 34.29,3.94 36.32,1.91 v38.48,1.91
  Bottom 1.778: D3.A 5.63,61.68 5.59,61.72 | 5.59,61.72 D1.A | 5.59,61.72 v5.59,59.82
  other vias: 39.88,54.36 36.96,54.23 36.96,52.2 79.5,18.54 77.47,16.76 39.88,52.58 36.96,50.17 36.2,13.59
  pour Top (isolate 0.254, no thermals): 19.56,59.69 19.56,49.28 21.34,47.5 26.42,47.5 30.23,51.31 33.66,51.31 35.31,52.96 35.31,57.02 35.69,57.4 75.69,57.4 81.28,62.99 83.82,62.99 91.69,70.87 107.7,70.87 108.46,70.36 108.46,31.5 107.95,30.99 105.03,30.99 104.65,31.37 104.65,32.89 103.25,34.29 101.6,34.29 100.2,32.89 100.2,7.11 99.7,6.6 83.06,6.6 76.96,12.7 76.96,19.05 77.22,19.3 80.01,19.3 80.26,19.05 80.26,13.97 84.07,10.16 96.52,10.16 97.79,11.43 97.79,34.04 93.98,37.85 85.85,37.85 83.44,40.26 83.44,46.23 82.3,47.37 84.46,49.53 93.98,49.53 95,50.55 95,58.42 93.98,59.44 84.07,59.44 83.06,58.42 83.06,50.67 84.2,49.53 82.17,47.5 81.92,47.75 61.85,47.75 57.79,43.69 53.34,43.69 52.96,44.07 52.96,48.64 48.51,53.09 45.09,53.09 40.51,48.51 35.43,48.51 30.61,43.69 14.22,43.69 13.72,44.2 13.72,49.53 10.16,53.09 1.27,53.09 0.76,53.59 0.76,61.98 1.27,62.48 16.76,62.48
  pour Bottom (no thermals): 86.61,5.46 86.61,9.65 87,10.03 97.66,10.03 98.04,9.65 98.04,5.46 97.79,5.21 86.87,5.21
  pour Bottom (no thermals): 42.42,48.51 36.83,48.51 35.31,50.04 35.31,54.86 35.81,55.37 40.64,55.37 43.18,52.83 43.18,49.28
  pour Bottom (no thermals): 75.57,19.3 84.07,19.3 84.33,19.05 84.33,17.02 83.82,16.51 81.28,16.51 80.77,16 75.57,16 75.18,16.38 75.18,18.92
  pour Top (no thermals): 49.4,16.13 45.85,16.13 45.59,16.38 45.59,21.08 45.21,21.46 38.23,21.46 37.59,20.83 37.59,5.97 37.34,5.72 33.91,5.72 33.66,5.97 33.66,12.83 31.24,15.24 31.24,24 31.62,24.38 36.07,24.38 37.08,25.4 37.08,29.34 37.47,29.72 41.53,29.72 41.91,30.1 41.91,31.62 43.69,33.4 50.8,33.4 53.21,30.99 55.37,30.99 55.75,30.61 55.75,26.29 55.25,25.78 50.93,25.78 49.78,24.64 49.78,16.51
  pour Bottom (isolate 0.254, no thermals): 66.17,23.24 60.2,23.24 59.94,23.5 59.94,26.92 59.69,27.18 57.79,27.18 57.66,27.31 57.66,28.45 57.79,28.58 66.29,28.58 66.55,28.32 66.55,23.62
  pour Bottom (no thermals): 53.21,28.45 55.37,28.45 55.5,28.32 55.5,27.81 55.37,27.69 53.21,27.69 53.09,27.81 53.09,28.32
  pour Bottom (no thermals): 28.19,60.45 28.19,61.98 28.45,62.23 32.64,62.23 33.02,61.85 33.02,60.58 32.64,60.2 28.45,60.2
  pour Bottom (no thermals): 45.47,39.62 48.26,42.42 50.42,42.42 51.56,43.56 53.47,43.56 53.72,43.31 53.72,40.64 53.47,40.39 52.45,40.39 51.82,41.02 48.9,41.02 48.13,40.26 48.13,36.83 47.88,36.58 43.31,36.58 42.93,36.96 42.93,39.37 43.18,39.62
  pour Top: 38.23,2.41 44.58,2.41 50.42,8.26 57.53,8.26 59.31,10.03 59.31,20.32 59.44,20.45 60.2,20.45 60.33,20.32 60.33,12.32 65.15,7.49 65.15,4.32 64.77,3.94 48.64,3.94 46.1,1.4 38.23,1.4 37.97,1.65 37.97,2.16
N$45
  Bottom 0.813: D13.C 50.29,32.13 51.82,30.61 51.82,29.85 | 51.82,29.85 R15.1 | 51.82,29.85 65.53,29.85 66.8,31.12 66.8,36.7 69.72,39.62 70.49,39.62
  Bottom 1.016: 70.49,39.62 U3.4
N$46
  Top 1.778: J1.+ 3.05,8.13 2.29,8.89 F1.1
N$47
  Bottom 0.61: U4.7 128.65,32.39 128.02,31.75 128.02,31.24 127.76,30.99
  Bottom 0.813: 127.76,30.99 R23.1
  Bottom 1.016: D14.C 123.7,33.27 125.98,30.99 127.76,30.99
N$48
  Bottom 1.778: D12.A 43.43,9.27 R10.2
N$49
  Bottom 1.016: Q7.B 39.69,6.54 40.13,6.1 R42.2 40.14,5.08 40.13,5.08 40.13,4.32 43.69,0.76 99.95,0.76 101.73,2.54 U2.3
N$50
  Bottom 0.61: U4.3 129.92,41.28 131.06,42.42 131.06,43.18
  Bottom 1.016: C29.1 132.97,43.05 133.1,43.18 R27.1 131.06,43.18 131.06,47.5 127,51.56 127,61.21 125.73,62.48 125.73,63.5 125.48,63.75 R34.1
N$51  (via drill 0.5)
  Top 0.813: v140.72,41.4 140.72,46.48 139.19,48.01 139.19,55.37 133.86,60.71 v133.86,61.98
  Bottom 0.813: 143.26,39.62 143,39.88
  Bottom 1.016: R35.1 133.6,63.75 133.86,63.5 v133.86,61.98 | 143.26,39.62 C30.1 140.97,39.62 | R26.1 140.97,39.62 | v140.72,41.4 140.72,39.88 140.97,39.62
N$52
  Bottom 1.016: R23.2 C25.1
N$53
  Bottom 0.61: U4.6 129.92,33.4 130.56,32.77 132.33,32.77 133.48,33.91
  Bottom 0.813: R32.1 138.18,30.99 | C25.2 135.77,31.62 133.48,33.91 133.1,34.29 133.1,34.8 C24.1
  Bottom 1.016: C25.2 R32.1
N$54  (via drill 0.5)
  Top 0.813: v141.48,47.75 140.72,48.51 140.72,56.9 R21.2
  Bottom 0.813: Z2.C 141.61,58.55 139.95,60.2 R21.2
  Bottom 1.27: 141.47,46.74 Q4.1 v141.47,47.75 v141.48,47.75
N$55
  Bottom 0.61: U4.1 127.38,40.39 126.49,41.28 122.81,41.28 121.03,43.06 C26.1
  Bottom 0.813: C26.1 121.03,44.19 122.56,45.72 122.56,51.69 121.92,52.32 121.92,52.83 121.96,52.88 Q9.B
N$56  (via drill 0.5)
  Top 0.61: v127.76,36.58 132.72,41.53 v135.13,41.53
  Top 0.813: v119.38,31.24 119.38,34.04 v120.65,35.31
  Top 1.016: v128.78,52.58 127.25,52.58 v122.17,57.66
  Bottom 0.61: v127.76,36.58 127.38,36.2 U4.8 127.19,34.74 127,34.54 124.71,34.54 123.95,35.31 122.43,35.31 | v120.65,35.31 122.43,35.31 | C28.1 122.17,37.34 122.43,37.08 122.43,35.31
  Bottom 0.813: R39.2 121.82,5.69 119.38,8.13 v119.38,31.24
  Bottom 1.016: v128.78,52.58 134.87,46.48 136.4,46.48 136.68,46.76 Q4.3 | 138.18,43.18 R30.1 R27.2 135.64,43.18 135.64,42.04 v135.13,41.53 | v122.17,57.66 120.4,59.44 120.4,63.5 120.14,63.75 R33.1 | R20.2 122.43,39.62 122.3,39.49 C28.1
  Bottom 1.422: R30.1 137.92,43.18 136.91,44.19 Q4.3
N$57
  Bottom 1.016: C26.2 R24.1
N$58
  Bottom 0.61: R24.2 128.78,43.18 128.65,43.05 U4.2
  Bottom 0.813: 128.52,46.23 128.52,47.24 124.71,51.05 R28.1 124.71,52.58
  Bottom 1.016: R29.2 128.52,46.23 128.68,46.08 R24.2
N$59
  Bottom 0.61: U4.5 131.19,35.94 131.83,36.58 135.13,36.58 135.64,36.07 135.64,35.05 135.89,34.8 C24.2
  Bottom 1.016: C24.2 137.92,34.8 | 137.92,34.8 R25.1 | R26.2 138.02,34.9 137.92,34.8
N$60
  Bottom 1.016: U2.4 101.47,5.08 99.19,2.79 68.2,2.79 67.95,3.05 R41.2
N$61
  Bottom 0.61: Q5.2 144.21,32.7 145.8,34.29 145.8,34.54 146.05,34.8 C22.2
  Bottom 0.813: Q5.2 141.67,32.7 140.97,32 140.97,30.99 R32.2
N$62
  Bottom 0.813: Q5.1 143.95,30.8 144.53,30.23 147.83,30.23 149.35,31.75 149.35,42.16 148.34,43.18 R31.1 145.8,43.18
N$63  (via drill 0.5)
  Top 0.813: 136.78,69.85 136.65,69.85 135.64,70.87 v135.64,72.64
  Top 1.422: v135.26,67.31 135.26,68.33 136.78,69.85 v139.32,69.85
  Bottom 0.813: v135.64,72.64 Q10.C | Q6.B 135.96,65.47 135.13,66.29 135.13,67.31 | 135.13,67.31 R38.2 | 135.13,67.31 v135.26,67.31
  Bottom 1.016: v139.32,69.85 140.84,68.33 140.84,67.18 140.87,67.21 R37.2
  Bottom 1.27: R37.2 140.87,65.43 140.59,65.15 140.59,63.37 140.56,63.35 R36.1
N$64
  Bottom 2.54: T1.2 107.07,24.9 112.65,30.48 JMP3.2
N$65
  Bottom 1.016: J3.+ 144.27,60.96 143.51,61.72 143.51,62.99 143.26,63.25 R36.2
N$66
  Bottom 1.27: JMP2.2 127.84,70.28 127.64,70.49 | 127.64,70.49 126.49,71.63 P1.2 | R35.2 130.91,64.92 128.27,67.56 128.27,69.85 127.64,70.49
N$67
  Bottom 1.27: 123.95,70.87 123.95,69.22 128.4,64.77 128.4,63.88 128.42,63.86 R34.2 | 123.95,70.87 P1.3 | JMP2.1 123.37,70.28 123.95,70.87
N$68
  Top 1.778: R21.1 130.3,54.61 132.84,54.61 C18.1
  Bottom 1.27: 124.71,55.37 R28.2 R21.1
  Bottom 1.422: C21.1 145.67,8 J2.-
  pour Bottom (isolate 0.61, no thermals): 133.35,50.29 130.56,53.09 130.56,57.66 131.06,58.17 139.83,58.17 141.35,56.64 149.61,56.64 150.11,56.13 150.11,50.8 149.61,50.29
  pour Top (no thermals): 141.73,49.02 141.73,58.17 142.24,58.67 147.07,58.67 147.57,58.17 147.57,34.54 146.56,33.53 146.56,29.46 146.05,28.96 143.76,28.96 142.49,27.69 142.49,25.53 143.76,24.26 149.61,24.26 149.99,23.88 149.99,7.49 149.61,7.11 137.41,7.11 136.91,7.62 136.91,15.11 137.29,15.49 140.59,15.49 143.26,18.16 143.26,22.1 140.34,25.02 136.02,25.02 135.64,25.4 135.64,28.96 138.68,32 138.68,34.54 140.72,36.58 140.72,39.37 141.99,40.64 141.99,46.74 142.49,47.24 142.49,48.26
  pour Bottom (no thermals): 136.91,10.16 136.91,16.26 137.29,16.64 139.32,16.64 139.7,16.26 139.7,13.46 142.11,11.05 142.11,10.16 141.86,9.91 137.16,9.91
N$69
  Bottom 1.27: P1.5 118.87,69.47 123.06,65.28 123.06,63.63 123.09,63.65 R33.2
N$70  (via drill 0.5)
  Top 0.61: v132.21,67.31 132.21,68.07 133.6,69.47 133.6,74.42 131.7,76.33 117.09,76.33 116.33,75.57 P1.6
  Bottom 0.813: 132.46,67.31 R38.1 v132.21,67.31
N$71
  Bottom 1.422: 15.49,28.96 R1B.2 R1A.1
N$72
  Bottom 0.813: D15.C 120.52,51.44 120.14,51.82 120.14,52.83 120.1,52.88 Q9.E
N$73
  Bottom 1.422: 68.45,11.43 R48.1 R49.2
N$74
  Bottom 1.422: C31.1 63.76,9.52 63.73,9.55 R49.1
N$75
  Bottom 0.813: Q10.B 139,73.59 136.4,76.2 115.06,76.2 114.43,75.57 114.43,71.25 118.36,67.31 118.36,58.8 121.03,56.13 Q9.C
N$76
  Bottom 0.813: C31.2 Z3.C 62.48,7.62 63.25,6.86 63.25,5.97 63.37,5.84 63.33,5.8 D17.2
N$77
  Bottom 0.813: U5.1 61.26,2.46 62.36,3.56 D17.3 63.8,3.6 64.64,4.45 C32.1 65.87,4.48 65.91,4.45 R44.2
N$79
  Bottom 0.813: R45.1 57.79,5.97 57.91,6.1 61.09,6.1 61.38,5.8 D17.1
N$80
  Bottom 0.61: R47.2 50.76,3.21 50.8,3.18 | 50.8,3.18 Q12.3 | 50.8,3.18 50.72,3.26 Q11.G 51.24,5.53 51.44,5.33 55.12,5.33 55.75,5.97 R45.2
N$81
  Bottom 0.61: R46.1 55.59,4.03 | Q12.1 54.04,4.13 54.1,4.06 | U5.2 58.23,2.47 56.68,4.03 C33.2
  Bottom 0.813: C33.2 55.63,4.06 55.59,4.03 | 54.1,4.06 R46.1

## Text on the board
tPlace: COM | ON Semiconductor | PWM IN | NCL30051 CVCC PSU | Rev 6 | Pb | L | +LED_A | N | -LED_C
